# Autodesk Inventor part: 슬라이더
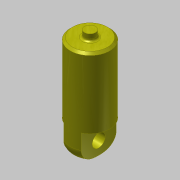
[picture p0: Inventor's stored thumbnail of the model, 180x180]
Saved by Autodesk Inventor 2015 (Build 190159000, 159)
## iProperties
Created: 2016-08
Part Number: 슬라이더
Material: 강철, 탄소
Document SubType Name: Modeling
Designer: mduedu
Density: 7.87 g/cm^3
Appearance: 노란색
Mass: 75.7832 g
Surface Area: 29.7429 cm^2
Volume: 9.62937 cm^3
Author: mduedu
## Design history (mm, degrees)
sketch "스케치1"
  geometry: C1 r 9 at (0, 0); 1 further point
  constraints: 1 centre point, 1 coincident
  dimensions: "d0" = 18 diameter of C1
extrude "돌출1" new body sketch "스케치1" distance "d1" = 45; taper "d2" = 0 deg
fillet "모깎기1" dims "d21" = 6
sketch "스케치6"
  geometry: L1 (9, 6)-(9, 45) reference; L2 (-9, 6)-(-9, 45) reference; L3 (9, 45)-(-9, 45) reference; L4 (0, 45)-(0, 0); L5 (9, 13)-(4, 13); L6 (4, 13)-(4, 0); L7 (4, 0)-(9, 0); L8 (9, 0)-(9, 13); L9 (-9, 13)-(-4, 13); L10 (-4, 13)-(-4, 0); L11 (-4, 0)-(-9, 0); L12 (-9, 0)-(-9, 13)
  constraints: 18 end point, 4 symmetric about line, 2 parallel, 2 perpendicular, 1 horizontal, 1 horizontal alignment, 1 midpoint, 1 point on line
  dimensions: "d22" = 13 distance of L7.end L5.start; "d24" = 4 distance between parallel lines of L6 L4
extrude "돌출5" cut sketch "스케치6" stored distance "d25" = 8; taper "d26" = 0 deg
sketch "스케치8"
  geometry: C1 r 3 at (6, 0); 1 further point
  constraints: 1 centre point, 1 horizontal alignment
  dimensions: "d27" = 6 diameter of C1; "d28" = 6 distance of point (0, 0) C1.centre
extrude "돌출6" cut sketch "스케치8" stored distance "d29" = 8; taper "d30" = 0 deg
chamfer "모따기2" distance "d43" = 1; stored, may be unused: second distance "d44" = 2, angle "d45" = 30 deg
sketch "스케치9"
  geometry: C1 r 2.5 at (0, 0); 1 further point
  constraints: 1 centre point, 1 coincident
  dimensions: "d47" = 5 diameter of C1
extrude "돌출7" join sketch "스케치9" distance "d48" = 3; taper "d49" = 0 deg
fillet "모깎기2" dims "d50" = 1
node "솔리드1"
